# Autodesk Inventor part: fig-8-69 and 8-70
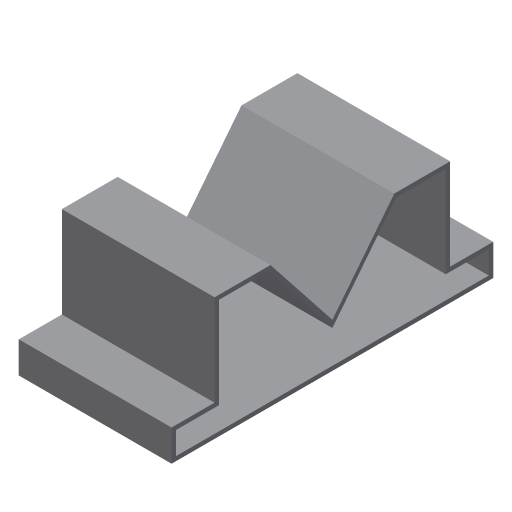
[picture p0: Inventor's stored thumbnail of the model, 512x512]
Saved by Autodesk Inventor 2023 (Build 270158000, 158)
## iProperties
Created: 2002-01
Part Number: fig-8-69 and 8-70
Document SubType Name: Modeling
Designer: ***
Density: 1 g/cm^3
Material: Generic
Appearance: Default
Control State: 0
Master: False
Checked Out: False
Shininess: 77.0
Length Units: 11269
Angle Units: 11279
Time Units: 11290
Mass Units: 11283
Length Display Precision: 3
Angle Display Precision: 2
Density: 0.0
Volumn: 0.0
Area: 0.0
PropertySet Name: Model Information
Author: ***
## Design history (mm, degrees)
node "Sketch1"
sketch "Sketch2"
  geometry: L1 (0, 0)-(-14.184, 17.961); L2 (-14.184, 17.961)-(-26.987, 17.961); L3 (-26.987, 17.961)-(-26.987, -2.947); L4 (-26.987, -2.947)-(-36.842, -2.947); L5 (-36.842, -2.947)-(-36.842, -10.132); L6 (26.987, 17.961)-(26.987, -2.947); L7 (14.184, 17.961)-(26.987, 17.961); L8 (26.987, -2.947)-(36.842, -2.947); L9 (36.842, -10.132)-(-36.842, -10.132); L10 (36.842, -2.947)-(36.842, -10.132); L11 (0, 0)-(14.184, 17.961)
  constraints: 22 end point, 2 horizontal, 2 parallel, 1 perpendicular
extrude "Extrusion1" new body sketch "Sketch2" distance "d0" = 35; taper "d1" = 0 deg
shell "Shell3" dims "d13" = 1
body "Solid1"
